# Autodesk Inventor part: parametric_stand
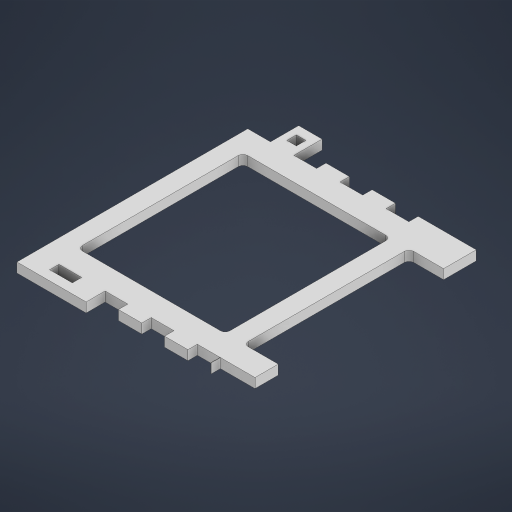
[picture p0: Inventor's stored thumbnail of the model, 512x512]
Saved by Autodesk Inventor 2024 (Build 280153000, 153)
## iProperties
Created: 2023-09
Part Number: parametric_stand
Material: Generic
Document SubType Name: Modeling
Designer: mammothbane
Density: 1 g/cm^3
Appearance: Default
Author: mammothbane
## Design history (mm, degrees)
sketch "sk_stand"
  geometry: L1 (0, 0)-(80, 0); L2 (80, 0)-(80, -100); L3 (80, -100)-(0, -100); L4 (0, -100)-(0, 0); L5 (72, -14.15)-(8, -14.15); L6 (8, -14.15)-(8, -85.85); L7 (8, -85.85)-(72, -85.85); L8 (72, -85.85)-(72, -14.15); L9 (0, 0)-(-15, 0); L10 (-15, 0)-(-15, -14.15); L11 (-15, -14.15)-(0, -14.15); L12 (0, -14.15)-(0, 0); L13 (0, -100)-(-15, -100); L14 (-15, -100)-(-15, -85.85); L15 (-15, -85.85)-(0, -85.85); L16 (0, -85.85)-(0, -100); L17 (80, -95.925)-(70.15, -95.925); L18 (70.15, -95.925)-(70.15, -100); L19 (70.15, -100)-(80, -100); L20 (80, -100)-(80, -95.925); L21 (70, 0)-(60.15, 0); L22 (60.15, 0)-(60.15, -4.075); L23 (60.15, -4.075)-(70, -4.075); L24 (70, -4.075)-(70, 0); L25 (0, -4.075)-(-15, -4.075); L26 (-15, -4.075)-(-15, 0); L27 (-15, 0)-(0, 0); L28 (0, 0)-(0, -4.075); L29 (75.075, -100)-(75.075, 0); L30 (65.075, -4.075)-(65.075, -100); 6 further points
  constraints: 60 end point, 16 parallel, 9 perpendicular, 7 horizontal, 7 point on line, 3 midpoint, 2 collinear
  dimensions: "d2" = 15 distance of L10.end L11.end (= leg_height); "d6" = 100 distance between parallel lines of L3 L1 (= width); "d7" = 8 distance between parallel lines of L2 L8 (computed from height, skel_scale); "d8" = 14.15 distance between parallel lines of L1 L5 (computed from edge_width, skel_scale, width); "d9" = 14.15 distance between parallel lines of L3 L7 (computed from edge_width, skel_scale, width); "d10" = 8 distance between parallel lines of L4 L6 (computed from height, skel_scale); "d11" = 80 distance between parallel lines of L4 L2 (= height); "d16" = 4.075 distance of L17.end L18.end (= edge_width_actual); "d29" = 4.075 distance between parallel lines of L9 L25 (= edge_width_actual); "d34" = 4.925 distance between parallel lines of L2 L29 (= 0.5 x edge_height_actual); "d35" = 10 distance between parallel lines of L29 L30 (= edge_height)
extrude "ext_stand" new body sketch "sk_stand" distance "d12" = 4.15 (= cardboard_thickness); taper "d13" = 0 deg
fillet "fillet_stand" dims "d14" = 2
extrude "ext_left_edge" cut sketch "sk_stand" distance "d19" = 4.15 (= cardboard_thickness); taper "d20" = 0 deg
pattern_linear "pat_left_edge" dims "d23" = -20 (= -2 x edge_height)
extrude "ext_right_edge" cut sketch "sk_stand" distance "d24" = 4.15 (= cardboard_thickness); taper "d25" = 0 deg
pattern_linear "pat_right_edge" dims "d28" = 20 (= 2 x edge_height)
extrude "foot_edge" cut sketch "sk_stand" distance "d30" = 4.15 (= cardboard_thickness); taper "d31" = 0 deg
sketch "sk_lock"
  geometry: L1 (-80, 95.925)-(-80, 0) reference; L2 (-80, 0)-(-50, 0); L3 (-50, 0)-(-50, -4.15); L4 (-50, -4.15)-(-80, -4.15); L5 (-80, -4.15)-(-80, 0); L6 (-80, 0)-(-70, 0) reference; 3 further points
  constraints: 8 end point, 2 midpoint, 2 parallel, 1 horizontal, 1 perpendicular
  dimensions: "d36" = 4.15 distance from line of point (-75, 0) L4 (= cardboard_thickness); "d37" = 30 distance from line of point (-80, -2.075) L3 (= 3 x edge_height)
extrude "ext_lock" join sketch "sk_lock" stored distance "d38" = 4.15 (= cardboard_thickness); taper "d39" = 0 deg
sketch "sk_key"
  geometry: L1 (-70.15, 100)-(-60, 100); L2 (-60, 100)-(-60, 108.15); L3 (-60, 108.15)-(-70.15, 108.15); L4 (-70.15, 108.15)-(-70.15, 100); L5 (-70.15, 95.925)-(-80, 95.925) reference; L6 (-80, 95.925)-(-80, -4.15) reference; L7 (-67.15, 100)-(-63, 100); L8 (-63, 100)-(-63, 104.15); L9 (-63, 104.15)-(-67.15, 104.15); L10 (-67.15, 104.15)-(-67.15, 100); L11 (-65.075, 104.15)-(-65.075, 100); 2 further points
  constraints: 18 end point, 4 parallel, 2 horizontal, 2 midpoint, 2 perpendicular, 1 point on line, 1 other
  dimensions: "d40" = 4.075 distance between parallel lines of L5 L1 (= edge_width_actual); "d41" = 9.85 distance between parallel lines of L6 L4 (= edge_height_actual); "d42" = 10.15 distance of L2.end L3.end (= edge_height + kerf); "d43" = 8.15 distance between parallel lines of L1 L3 (= 2 x cardboard_thickness - kerf); "d44" = 4.15 distance between parallel lines of L1 L9 (= cardboard_thickness); "d45" = 4.15 distance between parallel lines of L8 L10 (= cardboard_thickness)
extrude "ext_key" join sketch "sk_key" stored distance "d46" = 10; taper "d47" = 0 deg
node "stand"
other parameters: "height" = 80 [user parameter; used in 4 equation terms], "width" = 100 [user parameter; used in 3 equation terms], "leg_height" = 15 [user parameter; used in 1 equation term], "leg_width" = 15 [user parameter], "cardboard_thickness" = 4.15 [user parameter; used in 10 equation terms], "skel_scale" = 1 [user parameter; used in 4 equation terms], "edge_height" = 10 (computed from height, n_edge) [user parameter; used in 6 equation terms], "edge_width" = 4.15 (= cardboard_thickness) [user parameter; used in 3 equation terms], "kerf" = 0.15 [user parameter; used in 4 equation terms], "edge_height_actual" = 9.85 (= edge_height - kerf) [user parameter; used in 2 equation terms], "edge_width_actual" = 4.075 (= edge_width - 0.5 x kerf) [user parameter; used in 3 equation terms]
